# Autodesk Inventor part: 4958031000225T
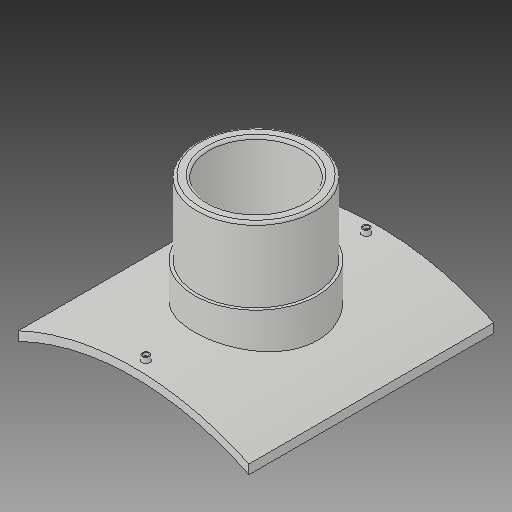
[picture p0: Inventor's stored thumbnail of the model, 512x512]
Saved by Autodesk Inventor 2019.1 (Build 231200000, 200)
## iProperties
Created: 2017-10
Part Number: 4958031000225T
Material: Generic
Description: PLASSON BRANCH SADDLE 1000x225
Document SubType Name: Modeling
Designer: KIM
Mass: 2754.05 g
Surface Area: 3037.44 cm^2
Volume: 2754.05 cm^3
Density: 1 g/cm^3
Appearance: Default
Author: KIM
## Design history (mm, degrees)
derived "495803.ipt"
feature "Solid1::495803.ipt"
tag "TaggingFeature1"
body "Solid1"
other parameters: "d1" = 16, "d2" = 443, "d4" = 0, "d12" = 525.6, "d13" = 14, "d14" = 211.5, "d16" = 5 deg, "d18" = 4, "d19" = 14, "d20" = 0, "d21" = 3, "d22" = 0, "d23" = 719, "d24" = 236.25, "d25" = 16, "d28" = 0, "d29" = 9.6, "d31" = 0, "d32" = 101.5, "d33" = 0, "d36" = 225, "d37" = 142.1, "d38" = 0, "d39" = 5, "d_1" = 225, "B_" = 443, "H_" = 203, "x_" = 16, "D_" = 16
